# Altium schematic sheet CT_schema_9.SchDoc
size 385 x 278 mm
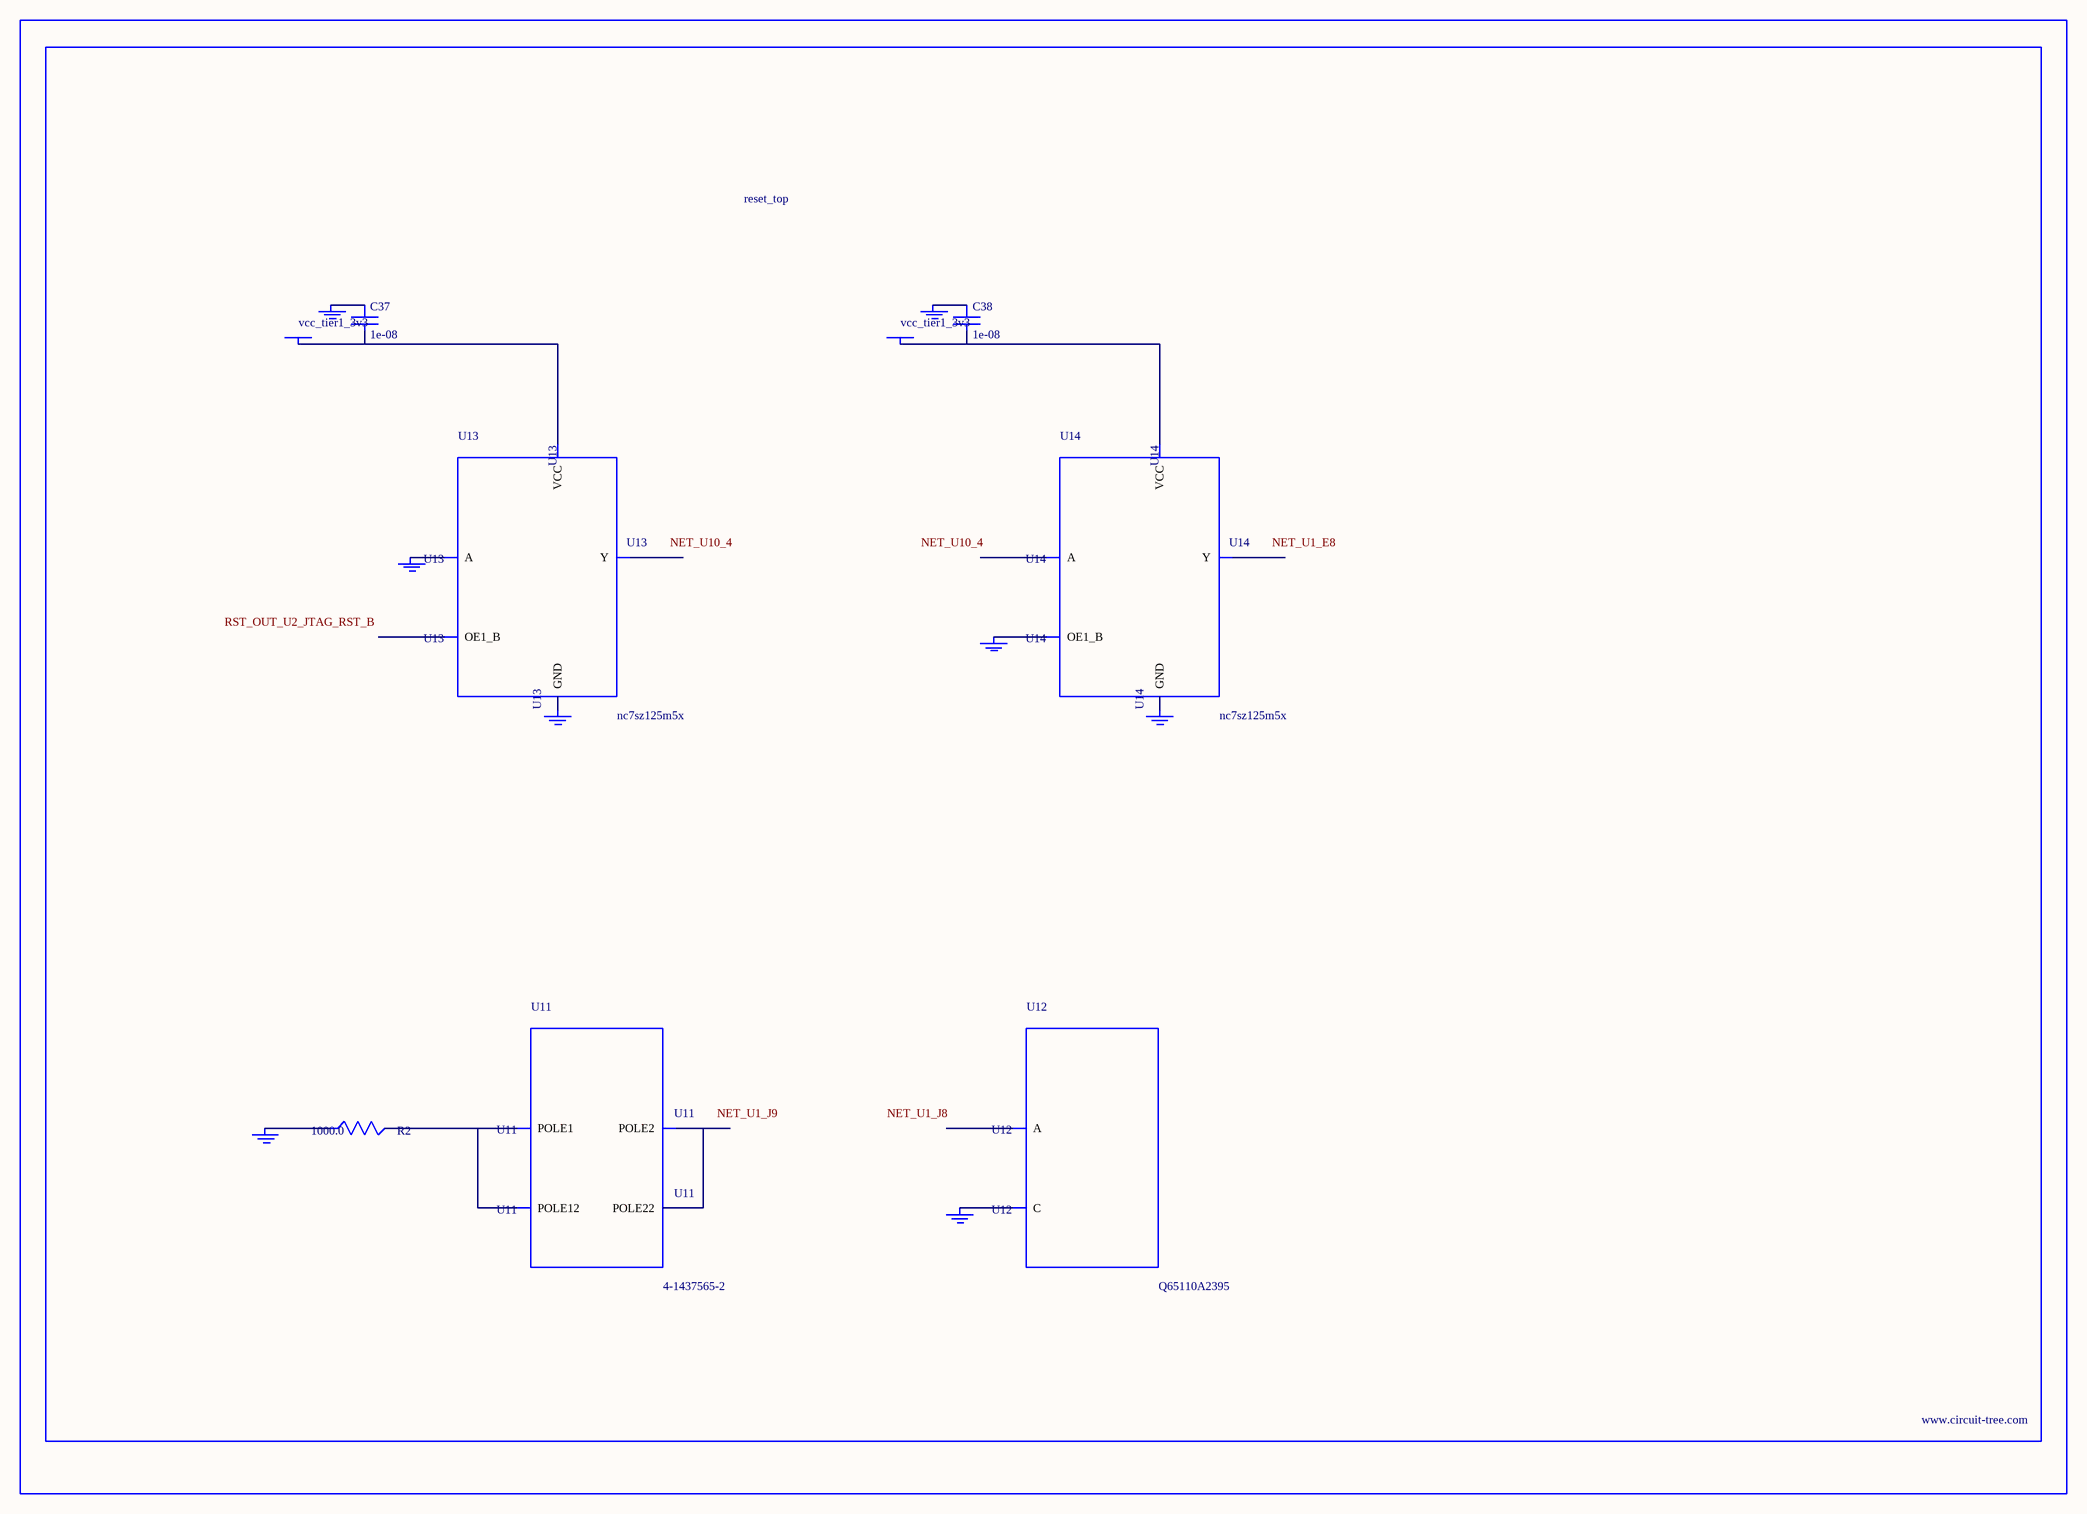
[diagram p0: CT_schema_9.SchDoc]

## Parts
BORDER8  (no value)
C37  1e-08  [C0402]
C38  1e-08  [C0402]
GND_INSTANCE_8_0  (no value)
GND_INSTANCE_8_1  (no value)
GND_INSTANCE_8_2  (no value)
GND_INSTANCE_8_3  (no value)
GND_INSTANCE_8_4  (no value)
GND_INSTANCE_8_5  (no value)
GND_INSTANCE_8_6  (no value)
GND_INSTANCE_8_7  (no value)
POWER_INSTANCE_8_0  vcc_tier1_3v3
POWER_INSTANCE_8_1  vcc_tier1_3v3
R2  1000.0  [R0603]
U11  4-1437565-2  [SW_4-1437565-2]
U12  Q65110A2395  [LGM67K-G1J2-24-Z]
U13  nc7sz125m5x  [NC7SZ125M5X]
U14  nc7sz125m5x  [NC7SZ125M5X]

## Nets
NetC37_1: C37.1 GND_INSTANCE_8_2.0(GND)
NetC37_2: C37.2 POWER_INSTANCE_8_0.0(PWR) U13.5(VCC)
NetC38_1: C38.1 GND_INSTANCE_8_5.0(GND)
NetC38_2: C38.2 POWER_INSTANCE_8_1.0(PWR) U14.5(VCC)
NetGND_INSTANCE_8_0_0: GND_INSTANCE_8_0.0(GND) R2.1
NetGND_INSTANCE_8_1_0: GND_INSTANCE_8_1.0(GND) U12.C
NetGND_INSTANCE_8_3_0: GND_INSTANCE_8_3.0(GND) U13.2(A)
NetGND_INSTANCE_8_4_0: GND_INSTANCE_8_4.0(GND) U13.3(GND)
NetGND_INSTANCE_8_6_0: GND_INSTANCE_8_6.0(GND) U14.1(OE1_B)
NetGND_INSTANCE_8_7_0: GND_INSTANCE_8_7.0(GND) U14.3(GND)
NetR2_2: R2.2 U11.1(POLE1) U11.2(POLE12)
NetU11_3: U11.3(POLE2) U11.4(POLE22)

Not connected (* = marked no-connect by the designer): U12 A; U13 1(OE1_B) 4(Y); U14 2(A) 4(Y)

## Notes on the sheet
- Labels drawn without touching a wire or pin: NET_U1_E8, NET_U1_J8, NET_U1_J9, NET_U10_4, RST_OUT_U2_JTAG_RST_B

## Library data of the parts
BORDER8 = BORDER_PAGE8
C37 C38 = C0402C103K3RAC
GND_INSTANCE_8_0-GND_INSTANCE_8_7 = GND
POWER_INSTANCE_8_0 POWER_INSTANCE_8_1 = PWR
R2 = RC0603JR-071KL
